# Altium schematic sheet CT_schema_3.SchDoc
size 294 x 169 mm
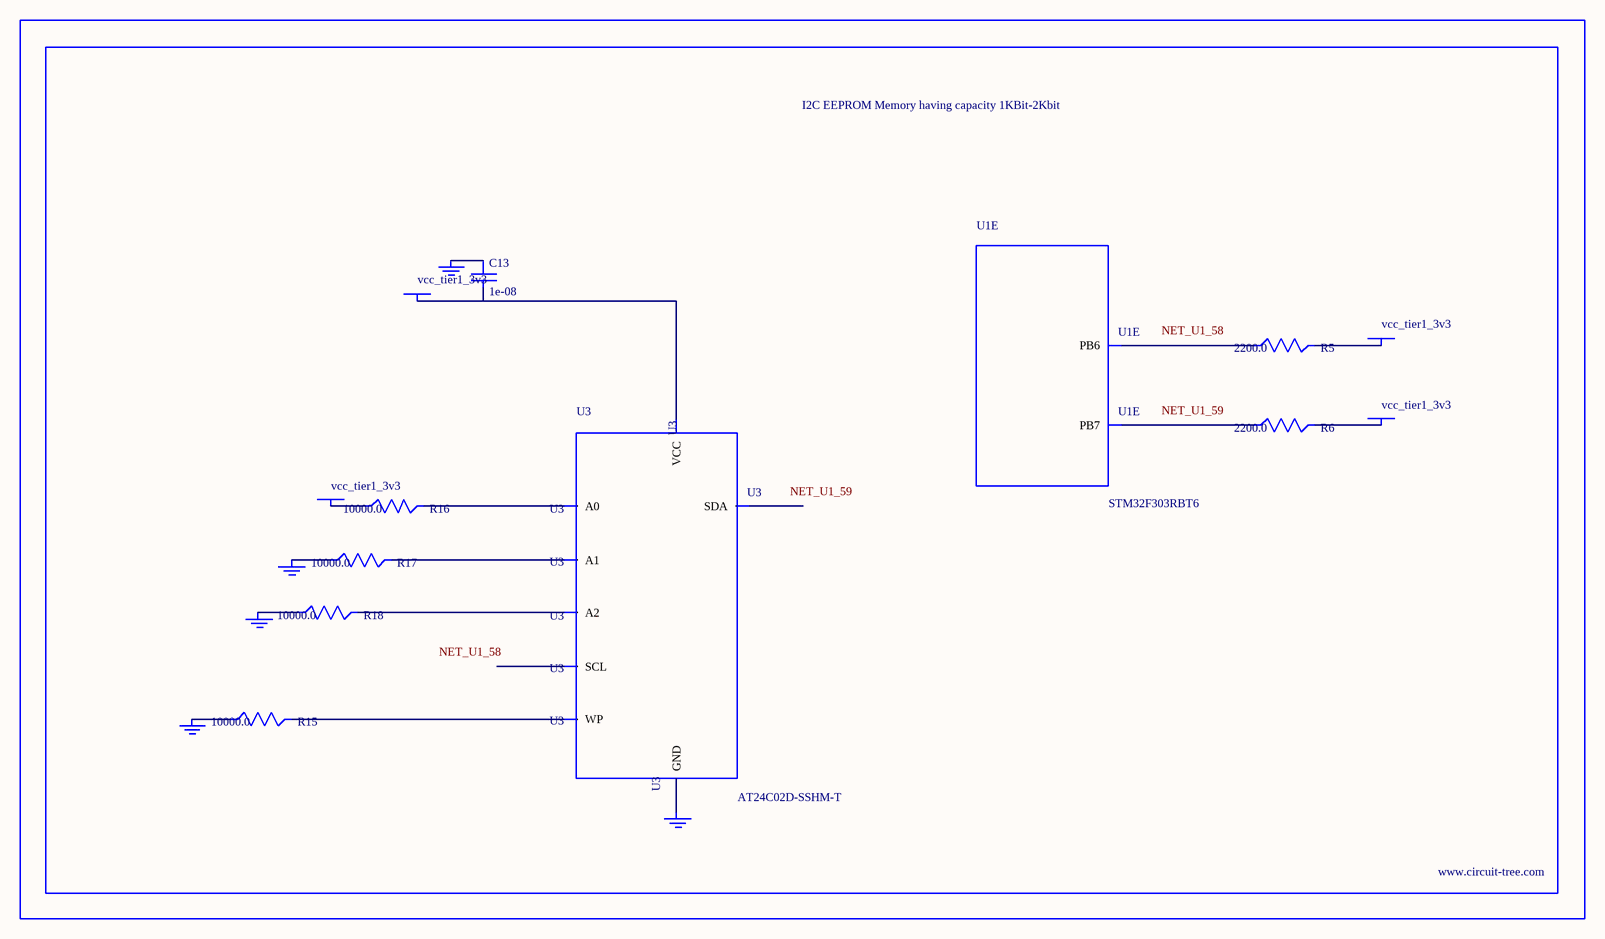
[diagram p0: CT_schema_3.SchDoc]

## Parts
BORDER2  (no value)
C13  1e-08  [C0402]
GND_INSTANCE_2_0  (no value)
GND_INSTANCE_2_1  (no value)
GND_INSTANCE_2_2  (no value)
GND_INSTANCE_2_3  (no value)
GND_INSTANCE_2_4  (no value)
POWER_INSTANCE_2_0  vcc_tier1_3v3
POWER_INSTANCE_2_1  vcc_tier1_3v3
POWER_INSTANCE_2_2  vcc_tier1_3v3
POWER_INSTANCE_2_3  vcc_tier1_3v3
R5  2200.0  [R0603]
R6  2200.0  [R0603]
R15  10000.0  [R0603]
R16  10000.0  [R0603]
R17  10000.0  [R0603]
R18  10000.0  [R0603]
U1  STM32F303RBT6  [LQFP64]  (part E of 7)
U3  AT24C02D-SSHM-T  [AT24C02D]

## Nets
NetC13_1: C13.1 GND_INSTANCE_2_3.0(GND)
NetC13_2: C13.2 POWER_INSTANCE_2_1.0(PWR) U3.8(VCC)
NetGND_INSTANCE_2_0_0: GND_INSTANCE_2_0.0(GND) R17.1
NetGND_INSTANCE_2_1_0: GND_INSTANCE_2_1.0(GND) R18.1
NetGND_INSTANCE_2_2_0: GND_INSTANCE_2_2.0(GND) R15.1
NetGND_INSTANCE_2_4_0: GND_INSTANCE_2_4.0(GND) U3.4(GND)
NetPOWER_INSTANCE_2_0_0: POWER_INSTANCE_2_0.0(PWR) R16.1
NetPOWER_INSTANCE_2_2_0: POWER_INSTANCE_2_2.0(PWR) R5.2
NetPOWER_INSTANCE_2_3_0: POWER_INSTANCE_2_3.0(PWR) R6.2
NetR5_1: R5.1 U1.58(PB6)
NetR6_1: R6.1 U1.59(PB7)
NetR15_2: R15.2 U3.7(WP)
NetR16_2: R16.2 U3.1(A0)
NetR17_2: R17.2 U3.2(A1)
NetR18_2: R18.2 U3.3(A2)

Not connected (* = marked no-connect by the designer): U3 5(SDA) 6(SCL)

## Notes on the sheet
- Labels drawn without touching a wire or pin: NET_U1_58, NET_U1_59

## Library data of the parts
BORDER2 = BORDER_PAGE2
C13 = C0402C103K3RAC
GND_INSTANCE_2_0-GND_INSTANCE_2_4 = GND
POWER_INSTANCE_2_0-POWER_INSTANCE_2_3 = PWR
R5 R6 = RC0603JR-072K2L
R15-R18 = RC0603JR-0710KL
